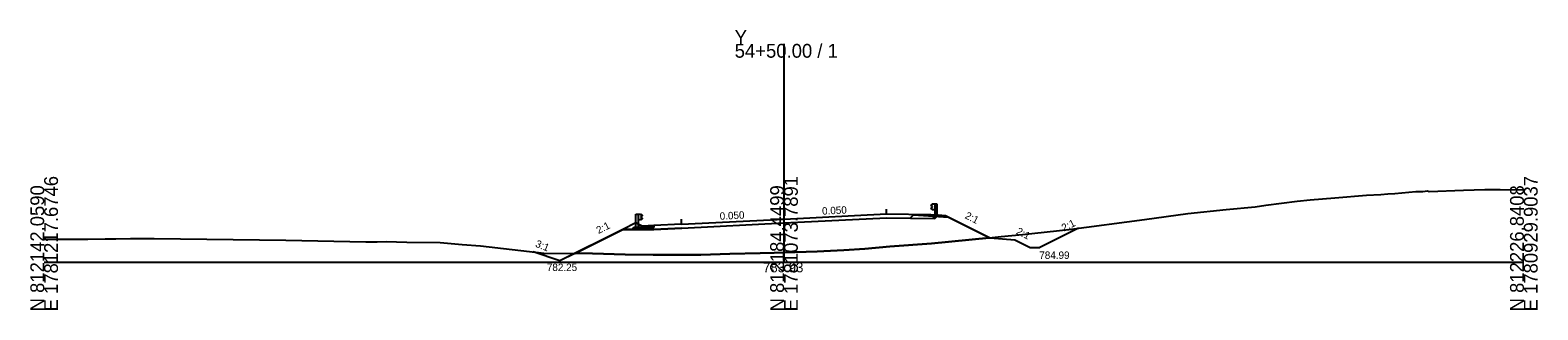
# Model space of a CAD drawing. Extents: x -12583 to 5303, y -44 to 25667.
# Drawn here: x 3997.2 to 4302.8, y 4990.3 to 5047.1 of the extents above; entities that cross this region are included whole.
import ezdxf

# ---------------------------------------------------------------- set-up
doc = ezdxf.new("R2010")
doc.units = 0
for name, color, linetype in [('Exist Cross Section Cell', 7, 'Continuous'), ('Exist XS Center Line Elevation Label', 7, 'Continuous'), ('Exist XS Ground Line', 7, 'Continuous'), ('Prop XS DDE', 7, 'Continuous'), ('Prop XS Ditch Standard Text', 7, 'Continuous'), ('Prop XS Dump Level', 7, 'Continuous'), ('Prop XS Earthwork Shape', 7, 'Continuous'), ('Prop XS EOT Tick Mark', 7, 'Continuous'), ('Prop XS Finish Grade', 7, 'Continuous'), ('Prop XS Finish Grade CurbGutter', 7, 'Continuous'), ('Prop XS Finish Grade Earthwork', 7, 'Continuous'), ('Prop XS Finish Grade Paved Shoulder', 7, 'Continuous'), ('Prop XS Finish Grade Pavement', 7, 'Continuous'), ('Prop XS Guardrail', 7, 'Continuous'), ('Prop XS Pvmt Edge Slope', 7, 'Continuous'), ('Prop XS SE Text', 7, 'Continuous'), ('Prop XS Side Slope Text', 7, 'Continuous'), ('Prop XS Subgrade CurbGutter', 7, 'Continuous'), ('Prop XS Subgrade Earthwork', 7, 'Continuous')]:
    doc.layers.add(name, color=color, linetype=linetype)

msp = doc.modelspace()

# ---------------------------------------------------------------- linework, layer by layer
at = {"layer": 'Exist Cross Section Cell'}
for p, q in [((4150, 5000), (4150, 5044.29)), ((4000, 5000), (4150, 5000)), ((4150, 5000), (4300, 5000))]:
    msp.add_line(p, q, dxfattribs=at)
at = {"layer": 'Exist XS Ground Line'}
for p, q in [((4261.66, 5013.07), (4268.13, 5013.61)), ((4268.13, 5013.61), (4270.98, 5013.74)), ((4270.98, 5013.74), (4272.41, 5013.85)), ((4272.41, 5013.85), (4273.82, 5013.92)), ((4273.82, 5013.92), (4276.67, 5014.2)), ((4276.67, 5014.2), (4278.1, 5014.32)), ((4278.1, 5014.32), (4279.1, 5014.35)), ((4279.1, 5014.35), (4279.54, 5014.35)), ((4279.54, 5014.35), (4280.44, 5014.44)), ((4280.44, 5014.44), (4280.78, 5014.36)), ((4280.78, 5014.36), (4287.77, 5014.6)), ((4287.77, 5014.6), (4292.1, 5014.76)), ((4292.1, 5014.76), (4295.22, 5014.73)), ((4295.22, 5014.73), (4300, 5014.7)), ((4231.9, 5009.85), (4239.63, 5010.7)), ((4239.63, 5010.7), (4245.51, 5011.2)), ((4245.51, 5011.2), (4247.72, 5011.53)), ((4247.72, 5011.53), (4254.04, 5012.34)), ((4254.04, 5012.34), (4256.7, 5012.67)), ((4256.7, 5012.67), (4261.66, 5013.07)), ((4207.76, 5006.64), (4223.08, 5008.67)), ((4223.08, 5008.67), (4231.9, 5009.85)), ((4000, 5004.68), (4000.98, 5004.69)), ((4000.98, 5004.69), (4002.07, 5004.69)), ((4002.07, 5004.69), (4005.48, 5004.69)), ((4005.48, 5004.69), (4006.44, 5004.69)), ((4006.44, 5004.69), (4008.46, 5004.69)), ((4008.46, 5004.69), (4008.85, 5004.69)), ((4008.85, 5004.69), (4012.35, 5004.71)), ((4012.35, 5004.71), (4014.54, 5004.73)), ((4014.54, 5004.73), (4017.49, 5004.77)), ((4017.49, 5004.77), (4022.33, 5004.82)), ((4022.33, 5004.82), (4048.98, 5004.46)), ((4048.98, 5004.46), (4065.2, 5004.11)), ((4065.2, 5004.11), (4067.5, 5004.14)), ((4067.5, 5004.14), (4069.35, 5004.18)), ((4069.35, 5004.18), (4073.54, 5004.04)), ((4073.54, 5004.04), (4080.26, 5004.01)), ((4080.26, 5004.01), (4084.77, 5003.57)), ((4179.91, 5003.76), (4191.59, 5004.91)), ((4191.59, 5004.91), (4194.01, 5005.2)), ((4194.01, 5005.2), (4198.34, 5005.63)), ((4198.34, 5005.63), (4207.76, 5006.64)), ((4084.77, 5003.57), (4088.47, 5003.34)), ((4088.47, 5003.34), (4101.3, 5001.81)), ((4101.3, 5001.81), (4111.17, 5001.73)), ((4111.17, 5001.73), (4117.78, 5001.54)), ((4117.78, 5001.54), (4123.49, 5001.48)), ((4123.49, 5001.48), (4126.21, 5001.47)), ((4126.21, 5001.47), (4133.14, 5001.48)), ((4133.14, 5001.48), (4139, 5001.69)), ((4139, 5001.69), (4145.15, 5001.83)), ((4145.15, 5001.83), (4148.01, 5001.86)), ((4148.01, 5001.86), (4150, 5001.93)), ((4150, 5001.93), (4156.71, 5002.16)), ((4156.71, 5002.16), (4162.13, 5002.44)), ((4162.13, 5002.44), (4166.4, 5002.68)), ((4166.4, 5002.68), (4171.47, 5003.14)), ((4171.47, 5003.14), (4179.91, 5003.76))]:
    msp.add_line(p, q, dxfattribs=at)
at = {"layer": 'Prop XS DDE'}
for p, q in [((4191.82, 5004.94), (4196.82, 5004.52)), ((4196.82, 5004.52), (4199.88, 5002.99)), ((4209.7, 5006.9), (4201.88, 5002.99)), ((4199.88, 5002.99), (4201.88, 5002.99))]:
    msp.add_line(p, q, dxfattribs=at)
at = {"layer": 'Prop XS Dump Level'}
for p, q in [((4129.25, 5007.7), (4150, 5008.74)), ((4150, 5008.74), (4170.75, 5009.77))]:
    msp.add_line(p, q, dxfattribs=at)
at = {"layer": 'Prop XS Earthwork Shape'}
for points in [[(4129.29, 5006.91), (4150.04, 5007.95), (4170.77, 5008.98), (4175.55, 5008.93), (4176.24, 5009.63), (4183.32, 5009.13), (4191.73, 5004.93), (4191.59, 5004.91), (4179.91, 5003.76), (4171.47, 5003.14), (4166.4, 5002.68), (4162.13, 5002.44), (4156.71, 5002.16), (4150, 5001.93), (4148.01, 5001.86), (4145.15, 5001.83), (4139, 5001.69), (4133.14, 5001.48), (4126.21, 5001.47), (4123.49, 5001.48), (4117.78, 5001.54), (4111.17, 5001.73), (4107.59, 5001.76), (4117.32, 5006.62), (4119.19, 5006.62), (4123.58, 5006.62)], [(4099.12, 5002.07), (4101.3, 5001.81), (4107.59, 5001.76), (4104.57, 5000.25)]]:
    msp.add_lwpolyline(points, close=True, dxfattribs=at)
at = {"layer": 'Prop XS EOT Tick Mark'}
for p, q in [((4170.75, 5009.77), (4170.75, 5010.77)), ((4129.25, 5007.7), (4129.25, 5008.7))]:
    msp.add_line(p, q, dxfattribs=at)
at = {"layer": 'Prop XS Finish Grade'}
for p, q in [((4119.98, 5007.95), (4117.32, 5006.62)), ((4120.56, 5007.66), (4119.98, 5007.95)), ((4179.75, 5009.68), (4181.24, 5009.58))]:
    msp.add_line(p, q, dxfattribs=at)
at = {"layer": 'Prop XS Finish Grade CurbGutter'}
for p, q in [((4121.25, 5007.32), (4120.56, 5007.66)), ((4123.58, 5007.42), (4121.25, 5007.32))]:
    msp.add_line(p, q, dxfattribs=at)
at = {"layer": 'Prop XS Finish Grade Earthwork'}
for p, q in [((4181.24, 5009.58), (4182.75, 5009.47)), ((4182.75, 5009.47), (4191.82, 5004.94)), ((4117.32, 5006.62), (4104.57, 5000.25)), ((4104.57, 5000.25), (4099.12, 5002.07))]:
    msp.add_line(p, q, dxfattribs=at)
at = {"layer": 'Prop XS Finish Grade Paved Shoulder'}
for p, q in [((4129.25, 5007.7), (4123.58, 5007.42)), ((4170.75, 5009.77), (4179.75, 5009.68))]:
    msp.add_line(p, q, dxfattribs=at)
at = {"layer": 'Prop XS Finish Grade Pavement'}
for p, q in [((4129.25, 5007.7), (4150, 5008.74)), ((4150, 5008.74), (4170.75, 5009.77))]:
    msp.add_line(p, q, dxfattribs=at)
at = {"layer": 'Prop XS Guardrail'}
for p, q in [((4179.78, 5011.59), (4179.75, 5011.53)), ((4179.75, 5011.53), (4179.78, 5011.47)), ((4179.78, 5010.98), (4179.75, 5010.92)), ((4179.75, 5010.92), (4179.78, 5010.86)), ((4180.07, 5011.79), (4179.78, 5011.59)), ((4179.78, 5011.47), (4180.07, 5011.27)), ((4180.07, 5011.18), (4179.78, 5010.98)), ((4179.78, 5010.86), (4180.07, 5010.66)), ((4180.57, 5011.79), (4180.07, 5011.79)), ((4180.07, 5011.27), (4180.07, 5011.18)), ((4180.07, 5010.66), (4180.57, 5010.66)), ((4181.07, 5011.79), (4180.57, 5011.79)), ((4180.57, 5011.79), (4180.57, 5009.29)), ((4181.07, 5009.29), (4181.07, 5011.79)), ((4119.93, 5009.72), (4120.43, 5009.72)), ((4119.93, 5007.22), (4119.93, 5009.72)), ((4120.43, 5009.72), (4120.93, 5009.72)), ((4120.43, 5009.72), (4120.43, 5007.22)), ((4120.93, 5008.58), (4120.43, 5008.58)), ((4120.93, 5009.72), (4121.22, 5009.52)), ((4121.22, 5009.4), (4120.93, 5009.2)), ((4120.93, 5009.2), (4120.93, 5009.1)), ((4120.93, 5009.1), (4121.22, 5008.9)), ((4121.22, 5008.78), (4120.93, 5008.58)), ((4121.22, 5009.52), (4121.25, 5009.46)), ((4121.25, 5009.46), (4121.22, 5009.4)), ((4121.22, 5008.9), (4121.25, 5008.84)), ((4121.25, 5008.84), (4121.22, 5008.78))]:
    msp.add_line(p, q, dxfattribs=at)
at = {"layer": 'Prop XS Pvmt Edge Slope'}
for p, q in [((4179.75, 5009.68), (4180.55, 5008.88)), ((4119.56, 5007), (4119.19, 5006.62)), ((4120.56, 5007), (4119.56, 5007))]:
    msp.add_line(p, q, dxfattribs=at)
at = {"layer": 'Prop XS Subgrade CurbGutter'}
for p, q in [((4120.56, 5007), (4120.56, 5007.66)), ((4123.58, 5007.42), (4123.58, 5007)), ((4123.58, 5007), (4120.56, 5007))]:
    msp.add_line(p, q, dxfattribs=at)
at = {"layer": 'Prop XS Subgrade Earthwork'}
for p, q in [((4129.29, 5006.91), (4150.04, 5007.95)), ((4150.04, 5007.95), (4170.77, 5008.98)), ((4170.77, 5008.98), (4180.55, 5008.88)), ((4180.55, 5008.88), (4181.24, 5009.58)), ((4119.19, 5006.62), (4117.32, 5006.62)), ((4123.58, 5006.62), (4119.19, 5006.62)), ((4129.29, 5006.91), (4123.58, 5006.62))]:
    msp.add_line(p, q, dxfattribs=at)

# ---------------------------------------------------------------- texts
at = {"layer": 'Exist Cross Section Cell'}
for s, p in [('Y', (4140, 5044.29)), ('54+50.00 / 1', (4140, 5041.49))]:
    msp.add_text(s, height=2.8, dxfattribs=at).set_placement(p)
for s, p in [('E 1781217.6746', (4002.8, 4990)), ('E 1781073.7891', (4152.8, 4990)), ('E 1780929.9037', (4302.8, 4990)), ('N 812142.0590', (4000, 4990)), ('N 812184.4499', (4150, 4990)), ('N 812226.8408', (4300, 4990))]:
    msp.add_text(s, height=2.8, rotation=90, dxfattribs=at).set_placement(p)
at = {"layer": 'Exist XS Center Line Elevation Label'}
msp.add_text('783.93', height=2, dxfattribs=at).set_placement((4145.75, 4997.93))
at = {"layer": 'Prop XS Ditch Standard Text'}
for s, p in [('784.99', (4201.76, 5000.66)), ('782.25', (4101.92, 4998.2))]:
    msp.add_text(s, height=1.5, dxfattribs=at).set_placement(p)
at = {"layer": 'Prop XS Dump Level'}
msp.add_text('Case2', height=0.04, dxfattribs=at).set_placement((4178.75, 5009.41))
at = {"layer": 'Prop XS SE Text'}
for p in [(4137, 5008.59), (4157.75, 5009.62)]:
    msp.add_text('0.050', height=1.5, rotation=2.8624, dxfattribs=at).set_placement(p)
at = {"layer": 'Prop XS Side Slope Text'}
for s, rotation, p in [('2:1', 333.4349, (4186.54, 5008.96)), ('2:1', 26.5651, (4112.4, 5005.69)), ('2:1', 26.5651, (4206.73, 5006.18)), ('3:1', 338.2006, (4099.46, 5003.17)), ('2:1', 333.4349, (4196.95, 5005.78))]:
    msp.add_text(s, height=1.5, rotation=rotation, dxfattribs=at).set_placement(p)

doc.saveas('drawing.dxf')
